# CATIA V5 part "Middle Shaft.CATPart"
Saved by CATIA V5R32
Part number: Middle shaft
Bounding box of the stored display mesh (mm): x 0 to 100, y -25 to 25, z -24.818 to 24.818
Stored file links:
  D:\PROJECTS\Project 2022\CATIA V5 6R 2022\Resources\Part Files\c16_catia_v5_6r2022_prt\Universal Joint-(Fig16-49)\Middle Shaft.CATPart
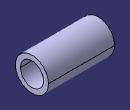
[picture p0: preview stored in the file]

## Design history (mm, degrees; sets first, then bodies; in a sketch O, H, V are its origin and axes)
Body1 (main body)
  Sketch1 on yz-plane, origin (0, 0, 0), H (0, 1, 0), V (0, 0, 1)
    circle A1 centre (0, 0) radius 25
    circle A2 centre (0, 0) radius 17.5
    radius A1 = 25
    radius A2 = 17.5
  Pad1: profile Sketch1, direction (1, 0, 0), length 100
